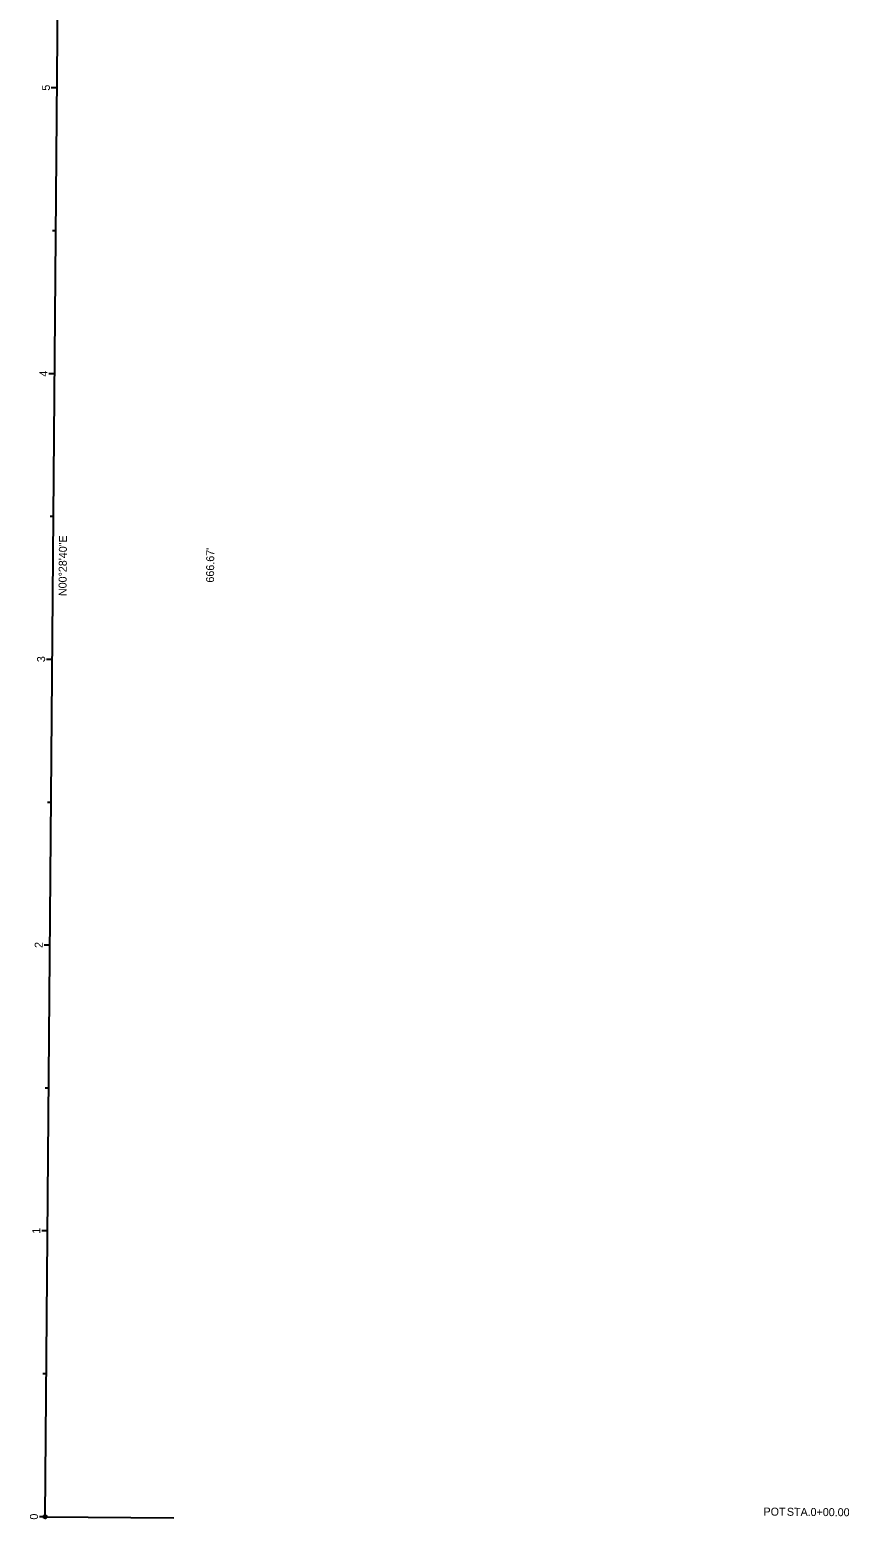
# Model space of a CAD drawing. Extents: x 1504629 to 1506299, y 325931 to 328016.
# Drawn here: x 1504629 to 1504915, y 325931 to 326452 of the extents above; entities that cross this region are included whole.
import ezdxf

# ---------------------------------------------------------------- set-up
doc = ezdxf.new("R2010")
doc.units = 0
for name, color, linetype in [('GE_X_Alignment', 7, 'Continuous'), ('GE_X_Alignment_100_Bearings', 7, 'Continuous'), ('GE_X_Alignment_100_Cardinal_Points', 7, 'Continuous'), ('GE_X_Alignment_100_Distances', 7, 'Continuous'), ('GE_X_Alignment_100_Stations', 7, 'Continuous')]:
    doc.layers.add(name, color=color, linetype=linetype)

msp = doc.modelspace()

# ---------------------------------------------------------------- linework, layer by layer
at = {"layer": 'GE_X_Alignment'}
msp.add_line((1504633.89, 325932.06), (1504639.45, 326598.71), dxfattribs=at)
at = {"layer": 'GE_X_Alignment_100_Cardinal_Points'}
msp.add_line((1504633.89, 325932.06), (1504678.89, 325931.69), dxfattribs=at)
msp.add_circle((1504633.89, 325932.06), 0.6, dxfattribs=at)
at = {"layer": 'GE_X_Alignment_100_Stations'}
for p, q in [((1504638.06, 326432.04), (1504636.06, 326432.06)), ((1504637.64, 326382.05), (1504636.44, 326382.06)), ((1504637.22, 326332.05), (1504635.22, 326332.06)), ((1504636.81, 326282.05), (1504635.61, 326282.06)), ((1504636.39, 326232.05), (1504634.39, 326232.07)), ((1504635.97, 326182.05), (1504634.77, 326182.06)), ((1504635.55, 326132.05), (1504633.55, 326132.07)), ((1504635.14, 326082.06), (1504633.94, 326082.07)), ((1504634.72, 326032.06), (1504632.72, 326032.08)), ((1504634.3, 325982.06), (1504633.1, 325982.07)), ((1504633.89, 325932.06), (1504631.89, 325932.08))]:
    msp.add_line(p, q, dxfattribs=at)

# ---------------------------------------------------------------- texts
at = {"layer": 'GE_X_Alignment_100_Bearings'}
msp.add_text('N00°28\'40"E', height=2.8, rotation=89.5221, dxfattribs=at).set_placement((1504641.37, 326254.23))
at = {"layer": 'GE_X_Alignment_100_Cardinal_Points'}
for s, p in [('POT', (1504885.07, 325932.48)), (' STA. ', (1504892.2, 325932.42)), ('0+00.00', (1504901.52, 325932.34))]:
    msp.add_text(s, height=2.8, rotation=359.5221, dxfattribs=at).set_placement(p)
at = {"layer": 'GE_X_Alignment_100_Distances'}
msp.add_text("666.67'", height=2.8, rotation=89.5221, dxfattribs=at).set_placement((1504692.95, 326258.95))
at = {"layer": 'GE_X_Alignment_100_Stations'}
for s, p in [('5', (1504635.55, 326431.09)), ('4', (1504634.71, 326331.02)), ('3', (1504633.88, 326231.11)), ('2', (1504633.05, 326131.1)), ('1', (1504632.21, 326031.09)), ('0', (1504631.38, 325931.05))]:
    msp.add_text(s, height=2.8, rotation=89.5221, dxfattribs=at).set_placement(p)

doc.saveas('drawing.dxf')
